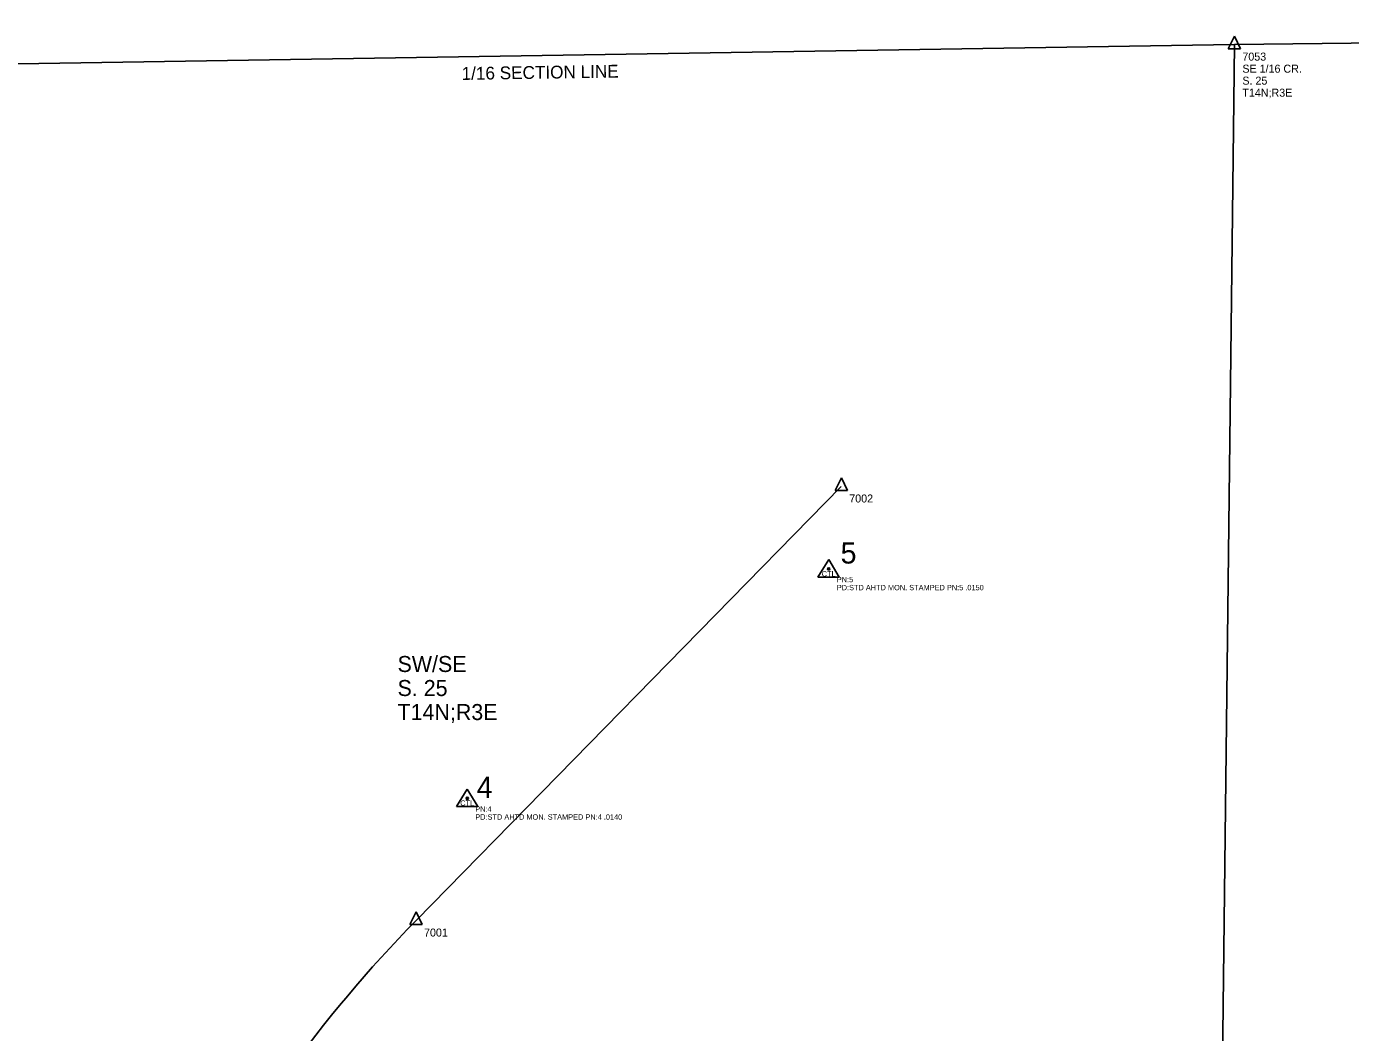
# Model space of a CAD drawing. Extents: x 1688544 to 1704497, y 535668 to 545444.
# Drawn here: x 1691347 to 1692588, y 539283 to 540226 of the extents above; entities that cross this region are included whole.
import ezdxf

# ---------------------------------------------------------------- set-up
doc = ezdxf.new("R2010")
doc.units = 0
for name, color, linetype in [('Default', 7, 'Continuous'), ('mjr no plot', 7, 'Continuous'), ('S_CAL_CORNER', 7, 'Continuous'), ('S_CAL_CORNER_ANNOT', 7, 'Continuous'), ('S_EXISTING_ALIGNMENT', 7, 'Continuous'), ('S_PRIMARY_CTL', 7, 'Continuous'), ('S_PRIMARY_CTL_ANNOT', 7, 'Continuous'), ('S_SECTION_ANNOT', 7, 'Continuous'), ('S_SIXTEEN_SECTION', 7, 'Continuous')]:
    doc.layers.add(name, color=color, linetype=linetype)

msp = doc.modelspace()

# ---------------------------------------------------------------- linework, layer by layer
at = {"layer": 'S_CAL_CORNER'}
for p, q in [((1692479.2, 540216.7), (1692473.4, 540204.8)), ((1692479.2, 540216.7), (1692473.4, 540204.8)), ((1692479.2, 540216.7), (1692473.4, 540204.8)), ((1692479.2, 540216.7), (1692485, 540204.8)), ((1692479.2, 540216.7), (1692485, 540204.8)), ((1692479.2, 540216.7), (1692485, 540204.8)), ((1692473.4, 540204.8), (1692485, 540204.8)), ((1692473.4, 540204.8), (1692485, 540204.8)), ((1692473.4, 540204.8), (1692485, 540204.8)), ((1692110.9, 539802.8), (1692105, 539790.9)), ((1692110.9, 539802.8), (1692105, 539790.9)), ((1692110.9, 539802.8), (1692116.7, 539790.9)), ((1692110.9, 539802.8), (1692116.7, 539790.9)), ((1692105, 539790.9), (1692116.7, 539790.9)), ((1692105, 539790.9), (1692116.7, 539790.9)), ((1691712.5, 539396.2), (1691706.6, 539384.4)), ((1691712.5, 539396.2), (1691706.6, 539384.4)), ((1691712.5, 539396.2), (1691718.3, 539384.4)), ((1691712.5, 539396.2), (1691718.3, 539384.4)), ((1691706.6, 539384.4), (1691718.3, 539384.4)), ((1691706.6, 539384.4), (1691718.3, 539384.4))]:
    msp.add_line(p, q, dxfattribs=at)
at = {"layer": 'S_EXISTING_ALIGNMENT'}
msp.add_line((1691712.4, 539388.2), (1692110.8, 539794.8), dxfattribs=at)
msp.add_arc((1692621.8, 538497.1), 1273.2, 135.5791, 169.7084, dxfattribs=at)
at = {"layer": 'S_PRIMARY_CTL'}
for p, q in [((1692099.1, 539726.3), (1692089, 539709.8)), ((1692099.1, 539726.3), (1692108.9, 539709.8)), ((1692089, 539709.8), (1692108.9, 539709.8)), ((1691760.4, 539511.4), (1691750.4, 539494.9)), ((1691760.4, 539511.4), (1691770.2, 539494.9)), ((1691750.4, 539494.9), (1691770.2, 539494.9))]:
    msp.add_line(p, q, dxfattribs=at)
for centre, radius in [((1692099.1, 539717.6), 1.04), ((1692099.1, 539717.6), 0.609), ((1692099.1, 539717.6), 0.344), ((1691760.4, 539502.7), 1.04), ((1691760.4, 539502.7), 0.609), ((1691760.4, 539502.7), 0.344)]:
    msp.add_circle(centre, radius, dxfattribs=at)
at = {"layer": 'S_SIXTEEN_SECTION'}
for p, q in [((1692479.1, 540208.7), (1693779.3, 540225.7)), ((1691185.3, 540188.2), (1692479.1, 540208.7)), ((1692463.7, 538893.2), (1692479.1, 540208.7))]:
    msp.add_line(p, q, dxfattribs=at)

# ---------------------------------------------------------------- texts
at = {"layer": 'Default'}
for s, p in [('SW/SE', (1691695.1, 539621)), ('S. 25', (1691695.1, 539598.5)), ('T14N;R3E', (1691695.1, 539576))]:
    msp.add_text(s, height=15, dxfattribs=at).set_placement(p)
at = {"layer": 'mjr no plot'}
for s, p in [('5', (1692110.2, 539722.6)), ('4', (1691769.2, 539503))]:
    msp.add_text(s, height=20, dxfattribs=at).set_placement(p)
at = {"layer": 'S_CAL_CORNER_ANNOT'}
for s, p in [('7053', (1692486.6, 540193.7)), ('SE 1/16 CR. ', (1692486.6, 540182.4)), ('T14N;R3E', (1692486.6, 540159.9)), ('S. 25', (1692486.6, 540171.2)), ('7002', (1692118.3, 539779.8)), ('7001', (1691719.9, 539373.2))]:
    msp.add_text(s, height=7.5, dxfattribs=at).set_placement(p)
at = {"layer": 'S_PRIMARY_CTL'}
for p in [(1692092.5, 539710.5), (1691753.8, 539495.7)]:
    msp.add_text('CTL', height=5, dxfattribs=at).set_placement(p)
at = {"layer": 'S_PRIMARY_CTL_ANNOT'}
for s, p in [('PN:5', (1692106.6, 539705.1)), ('PD:STD AHTD MON. STAMPED PN:5 .0150', (1692106.6, 539697.6)), ('PN:4', (1691767.9, 539490.2)), ('PD:STD AHTD MON. STAMPED PN:4 .0140', (1691767.9, 539482.7))]:
    msp.add_text(s, height=5, dxfattribs=at).set_placement(p)
at = {"layer": 'S_SECTION_ANNOT'}
msp.add_text('1/16 SECTION LINE', height=12, rotation=0.8773, dxfattribs=at).set_placement((1691755.2, 540175.6))

doc.saveas('drawing.dxf')
